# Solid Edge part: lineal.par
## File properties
Title: Lineal
Subject: Schmiege
Author: rauh
Template: normal.par
Last saved by: ra-tv
Revision: 2
Application: Solid Edge
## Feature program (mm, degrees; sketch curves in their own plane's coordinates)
sketch for "unnamed Protrusion 1" plane through (0, 0, 0) normal (0, 0, 1) x-axis (1, 0, 0)
  line (-30.6667, -18.1333) -> (119.3333, -18.1333)
  line (119.3333, -18.1333) -> (119.3333, -30.6333)
  line (119.3333, -30.6333) -> (114.3333, -30.6333)
  line (114.3333, -30.6333) -> (114.3333, -43.1333)
  line (114.3333, -43.1333) -> (-30.6667, -43.1333)
  line (-30.6667, -43.1333) -> (-30.6667, -18.1333)
extrude "unnamed Protrusion 1" add finite 5 symmetric
fillet "unnamed Round 1"
sketch for "unnamed Cutout 1" #1 plane through (44.3333, -30.6333, 2.5) normal (0, 0, 1) x-axis (1, 0, 0)
  circle centre (-40, 0) radius 4.5
sketch for "unnamed Cutout 1" #2 plane through (44.3333, -30.6333, 2.5) normal (0, 0, 1) x-axis (1, 0, 0)
  circle centre (50, 0) radius 4.5
extrude "unnamed Cutout 1" cut finite 76.2 symmetric
sketch for "unnamed Cutout 2" plane through (44.3333, -30.6333, 2.5) normal (0, 0, 1) x-axis (1, 0, 0)
  line (-40, 4.5) -> (50, 4.5)
  line (50, 4.5) -> (50, -4.5)
  line (50, -4.5) -> (-40, -4.5)
  line (-40, -4.5) -> (-40, 4.5)
extrude "unnamed Cutout 2" cut finite 247.65 symmetric
